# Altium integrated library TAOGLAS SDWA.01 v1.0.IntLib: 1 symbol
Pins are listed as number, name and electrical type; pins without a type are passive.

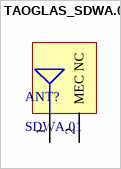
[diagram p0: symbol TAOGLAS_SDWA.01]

## TAOGLAS_SDWA.01
designator ANT?, comment SDWA.01
2.4/5-7.125GHz Wi-Fi® (Including Wi-Fi® 6) Ceramic SMD Antenna; ComponentLibStatus: Created; MFG: Taoglas; Temp_Low: -40C; Temp_High: +85C
footprint TAOGLAS_SDWA.01 (2.4/5-7.125GHz Wi-Fi® (Including Wi-Fi® 6) Ceramic SMD Antenna)
pins: 1 RF FEED, 2 MEC NC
